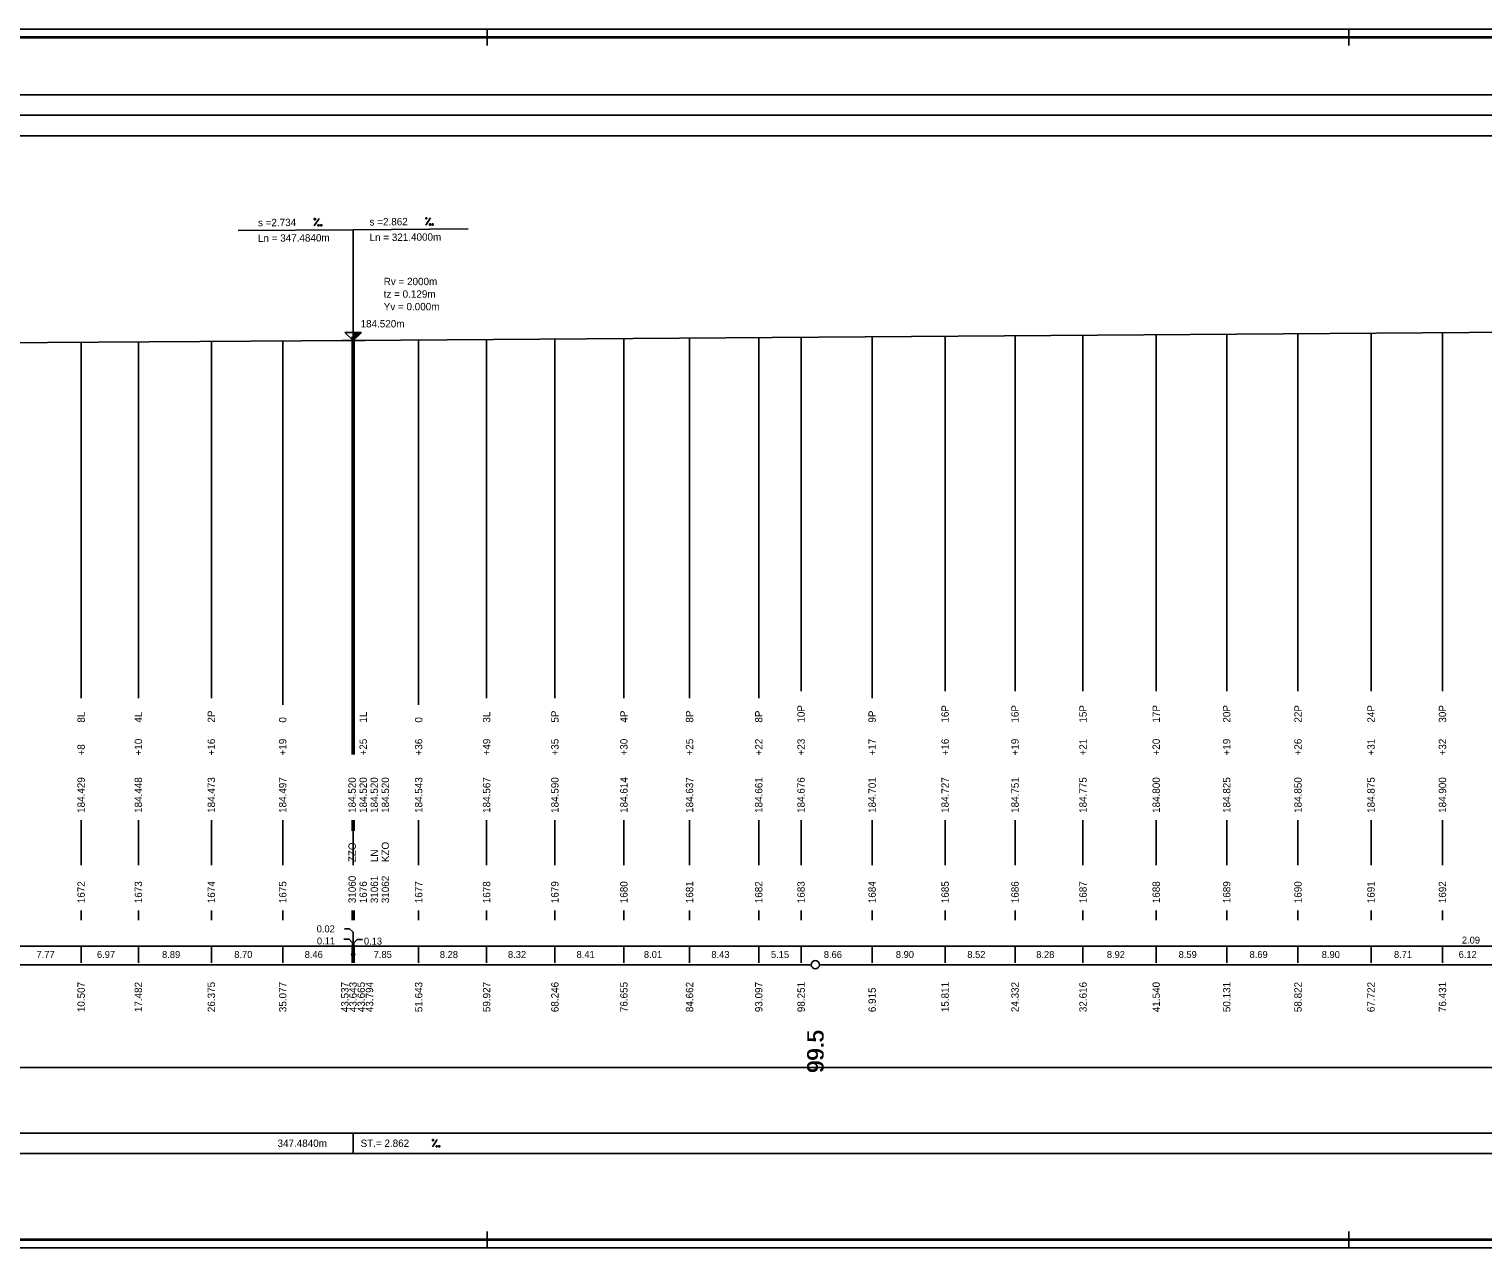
# Model space of a CAD drawing. Extents: x 0 to 10087, y -805 to 297.
# Drawn here: x 6188.3 to 6542.7, y 0 to 297 of the extents above; entities that cross this region are included whole.
import ezdxf

# ---------------------------------------------------------------- set-up
doc = ezdxf.new("R2010")
doc.units = 0
for name, color, linetype in [('CARKY_HODNOT', 7, 'Continuous'), ('KRIV1_CARA', 7, 'Continuous'), ('NIVELETA_CARA', 7, 'Continuous'), ('NIVELETA_TEXT', 7, 'Continuous'), ('RAM', 7, 'Continuous'), ('REZERVA', 7, 'Continuous'), ('STAN_CARA', 7, 'Continuous'), ('STAN_PAS', 7, 'Continuous'), ('STAN_TEXT', 7, 'Continuous'), ('TEXT', 7, 'Continuous'), ('TXT_C_BODU', 7, 'Continuous')]:
    doc.layers.add(name, color=color, linetype=linetype)

msp = doc.modelspace()

# ---------------------------------------------------------------- linework, layer by layer
at = {"layer": 'CARKY_HODNOT'}
for p, q in [((6201.01, 138.35), (6201.01, 220.65)), ((6214.96, 138.35), (6214.96, 220.74)), ((6232.75, 138.35), (6232.75, 220.86)), ((6250.15, 138.35), (6250.15, 220.98)), ((6267.07, 138.35), (6267.07, 221.1)), ((6267.29, 138.35), (6267.29, 221.1)), ((6267.33, 138.35), (6267.33, 221.1)), ((6267.59, 138.35), (6267.59, 221.1)), ((6283.29, 138.35), (6283.29, 221.21)), ((6299.85, 138.35), (6299.85, 221.33)), ((6316.49, 138.35), (6316.49, 221.45)), ((6333.31, 138.35), (6333.31, 221.57)), ((6349.32, 138.35), (6349.32, 221.69)), ((6366.19, 138.35), (6366.19, 221.81)), ((6376.5, 138.35), (6376.5, 221.88)), ((6393.83, 138.35), (6393.83, 222.01)), ((6411.62, 138.35), (6411.62, 222.13)), ((6428.66, 138.35), (6428.66, 222.25)), ((6445.23, 138.35), (6445.23, 222.37)), ((6463.08, 138.35), (6463.08, 222.5)), ((6480.26, 138.35), (6480.26, 222.62)), ((6497.64, 138.35), (6497.64, 222.75)), ((6515.44, 138.35), (6515.44, 222.88)), ((6532.86, 138.35), (6532.86, 223)), ((6201.01, 134), (6201.01, 138.35)), ((6214.96, 134), (6214.96, 138.35)), ((6232.75, 134), (6232.75, 138.35)), ((6250.15, 132.35), (6250.15, 138.35)), ((6267.07, 126.2), (6267.07, 138.35)), ((6267.29, 134), (6267.29, 138.35)), ((6267.33, 126.2), (6267.33, 138.35)), ((6267.59, 126.2), (6267.59, 138.35)), ((6283.29, 132.35), (6283.29, 138.35)), ((6299.85, 134), (6299.85, 138.35)), ((6316.49, 134), (6316.49, 138.35)), ((6333.31, 134), (6333.31, 138.35)), ((6349.32, 134), (6349.32, 138.35)), ((6366.19, 134), (6366.19, 138.35)), ((6376.5, 135.65), (6376.5, 138.35)), ((6393.83, 134), (6393.83, 138.35)), ((6411.62, 135.65), (6411.62, 138.35)), ((6428.66, 135.65), (6428.66, 138.35)), ((6445.23, 135.65), (6445.23, 138.35)), ((6463.08, 135.65), (6463.08, 138.35)), ((6480.26, 135.65), (6480.26, 138.35)), ((6497.64, 135.65), (6497.64, 138.35)), ((6515.44, 135.65), (6515.44, 138.35)), ((6532.86, 135.65), (6532.86, 138.35)), ((6267.07, 120.25), (6267.07, 126.2)), ((6267.33, 120.25), (6267.33, 126.2)), ((6267.59, 120.25), (6267.59, 126.2)), ((6201.01, 93.3), (6201.01, 104.2)), ((6214.96, 93.3), (6214.96, 104.2)), ((6232.75, 93.3), (6232.75, 104.2)), ((6250.15, 93.3), (6250.15, 104.2)), ((6267.07, 101.65), (6267.07, 104.2)), ((6267.29, 93.3), (6267.29, 104.2)), ((6267.33, 100), (6267.33, 104.2)), ((6267.59, 101.65), (6267.59, 104.2)), ((6283.29, 93.3), (6283.29, 104.2)), ((6299.85, 93.3), (6299.85, 104.2)), ((6316.49, 93.3), (6316.49, 104.2)), ((6333.31, 93.3), (6333.31, 104.2)), ((6349.32, 93.3), (6349.32, 104.2)), ((6366.19, 93.3), (6366.19, 104.2)), ((6376.5, 93.3), (6376.5, 104.2)), ((6393.83, 93.3), (6393.83, 104.2)), ((6411.62, 93.3), (6411.62, 104.2)), ((6428.66, 93.3), (6428.66, 104.2)), ((6445.23, 93.3), (6445.23, 104.2)), ((6463.08, 93.3), (6463.08, 104.2)), ((6480.26, 93.3), (6480.26, 104.2)), ((6497.64, 93.3), (6497.64, 104.2)), ((6515.44, 93.3), (6515.44, 104.2)), ((6532.86, 93.3), (6532.86, 104.2)), ((6201.01, 79.9), (6201.01, 82.2)), ((6214.96, 79.9), (6214.96, 82.2)), ((6232.75, 79.9), (6232.75, 82.2)), ((6250.15, 79.9), (6250.15, 82.2)), ((6267.07, 79.9), (6267.07, 82.2)), ((6267.29, 79.9), (6267.29, 82.2)), ((6267.33, 79.9), (6267.33, 82.2)), ((6267.59, 79.9), (6267.59, 82.2)), ((6283.29, 79.9), (6283.29, 82.2)), ((6299.85, 79.9), (6299.85, 82.2)), ((6316.49, 79.9), (6316.49, 82.2)), ((6333.31, 79.9), (6333.31, 82.2)), ((6349.32, 79.9), (6349.32, 82.2)), ((6366.19, 79.9), (6366.19, 82.2)), ((6376.5, 79.9), (6376.5, 82.2)), ((6393.83, 79.9), (6393.83, 82.2)), ((6411.62, 79.9), (6411.62, 82.2)), ((6428.66, 79.9), (6428.66, 82.2)), ((6445.23, 79.9), (6445.23, 82.2)), ((6463.08, 79.9), (6463.08, 82.2)), ((6480.26, 79.9), (6480.26, 82.2)), ((6497.64, 79.9), (6497.64, 82.2)), ((6515.44, 79.9), (6515.44, 82.2)), ((6532.86, 79.9), (6532.86, 82.2))]:
    msp.add_line(p, q, dxfattribs=at)
at = {"layer": 'KRIV1_CARA'}
msp.add_line((5093.47, 44), (6545.11, 44), dxfattribs=at)
at = {"layer": 'NIVELETA_CARA'}
for p, q in [((300, 281), (8321.33, 281)), ((300, 276), (8321.33, 276)), ((300, 271), (8321.33, 271)), ((6267.33, 248.1), (6239.33, 247.91)), ((6267.33, 248.1), (6295.33, 248.3)), ((6267.33, 221.1), (6267.33, 248.1)), ((6267.59, 221.1), (6909.24, 225.69)), ((5576.72, 216.38), (6267.07, 221.1)), ((6267.07, 221.1), (6264.53, 221.08)), ((6267.33, 221.1), (6265.33, 223.1)), ((6265.33, 223.1), (6269.33, 223.1)), ((6267.07, 221.1), (6267.07, 222.1)), ((6267.07, 221.1), (6267.33, 221.1)), ((6267.33, 221.1), (6267.33, 223.1)), ((6269.33, 223.1), (6267.33, 221.1)), ((6267.33, 221.1), (6267.59, 221.1)), ((6267.4, 221.17), (6267.4, 223.1)), ((6267.46, 221.23), (6267.46, 223.1)), ((6267.53, 221.3), (6267.53, 223.1)), ((6267.59, 221.1), (6267.59, 222.1)), ((6270.13, 221.12), (6267.59, 221.1)), ((6267.6, 221.37), (6267.6, 223.1)), ((6267.66, 221.43), (6267.66, 223.1)), ((6267.73, 221.5), (6267.73, 223.1)), ((6267.8, 221.57), (6267.8, 223.1)), ((6267.86, 221.63), (6267.86, 223.1)), ((6267.93, 221.7), (6267.93, 223.1)), ((6268, 221.77), (6268, 223.1)), ((6268.06, 221.83), (6268.06, 223.1)), ((6268.13, 221.9), (6268.13, 223.1)), ((6268.2, 221.97), (6268.2, 223.1)), ((6268.26, 222.03), (6268.26, 223.1)), ((6268.33, 222.1), (6268.33, 223.1)), ((6268.4, 222.17), (6268.4, 223.1)), ((6268.46, 222.23), (6268.46, 223.1)), ((6268.53, 222.3), (6268.53, 223.1)), ((6268.6, 222.37), (6268.6, 223.1)), ((6268.66, 222.43), (6268.66, 223.1)), ((6268.73, 222.5), (6268.73, 223.1)), ((6268.8, 222.57), (6268.8, 223.1)), ((6268.86, 222.63), (6268.86, 223.1)), ((6268.93, 222.7), (6268.93, 223.1)), ((6269, 222.77), (6269, 223.1)), ((6269.06, 222.83), (6269.06, 223.1)), ((6269.13, 222.9), (6269.13, 223.1)), ((6269.2, 222.97), (6269.2, 223.1)), ((6269.26, 223.03), (6269.26, 223.1)), ((500, 28), (8321.33, 28)), ((6267.33, 23), (6267.33, 28)), ((500, 23), (8321.33, 23))]:
    msp.add_line(p, q, dxfattribs=at)
at = {"layer": 'NIVELETA_TEXT'}
for p, q in [((6257.82, 250.83), (6257.82, 250.53)), ((6257.83, 250.83), (6257.82, 250.83)), ((6257.82, 250.53), (6258.12, 250.54)), ((6257.83, 249.04), (6259.01, 250.84)), ((6258.12, 250.83), (6257.83, 250.83)), ((6258.12, 250.54), (6258.12, 250.83)), ((6258.74, 249.34), (6258.74, 249.04)), ((6259.04, 249.34), (6258.74, 249.34)), ((6258.74, 249.34), (6258.74, 249.34)), ((6258.74, 249.04), (6259.04, 249.05)), ((6259.04, 249.05), (6259.04, 249.34)), ((6259.36, 249.34), (6259.35, 249.34)), ((6259.35, 249.34), (6259.35, 249.05)), ((6259.35, 249.05), (6259.65, 249.05)), ((6259.65, 249.35), (6259.36, 249.34)), ((6259.65, 249.05), (6259.65, 249.35)), ((6285.02, 251.02), (6285.02, 250.73)), ((6285.03, 251.02), (6285.02, 251.02)), ((6285.02, 250.73), (6285.32, 250.73)), ((6285.03, 249.23), (6286.21, 251.03)), ((6285.32, 251.03), (6285.03, 251.02)), ((6285.32, 250.73), (6285.32, 251.03)), ((6285.94, 249.53), (6285.94, 249.24)), ((6286.24, 249.53), (6285.94, 249.53)), ((6285.94, 249.53), (6285.94, 249.53)), ((6285.94, 249.24), (6286.24, 249.24)), ((6286.24, 249.24), (6286.24, 249.53)), ((6286.55, 249.54), (6286.55, 249.24)), ((6286.56, 249.54), (6286.55, 249.53)), ((6286.55, 249.24), (6286.85, 249.24)), ((6286.85, 249.54), (6286.56, 249.54)), ((6286.85, 249.24), (6286.85, 249.54)), ((6286.63, 24.6), (6287.82, 26.4)), ((6286.63, 26.4), (6286.63, 26.1)), ((6286.64, 26.4), (6286.63, 26.39)), ((6286.63, 26.1), (6286.93, 26.1)), ((6286.93, 26.4), (6286.64, 26.4)), ((6286.93, 26.1), (6286.93, 26.4)), ((6287.54, 24.9), (6287.54, 24.6)), ((6287.55, 24.9), (6287.54, 24.89)), ((6287.84, 24.9), (6287.55, 24.9)), ((6287.84, 24.6), (6287.84, 24.9)), ((6288.15, 24.9), (6288.15, 24.6)), ((6288.16, 24.9), (6288.15, 24.89)), ((6288.45, 24.9), (6288.16, 24.9)), ((6288.45, 24.6), (6288.45, 24.9)), ((6287.54, 24.6), (6287.84, 24.6)), ((6288.15, 24.6), (6288.45, 24.6))]:
    msp.add_line(p, q, dxfattribs=at)
at = {"layer": 'RAM'}
for p, q in [((8636.33, 297), (0, 297)), ((8634.33, 295.1), (2, 295.1)), ((8634.33, 295), (2, 295)), ((8634.33, 294.9), (2, 294.9)), ((6300, 293), (6300, 297)), ((6510, 293), (6510, 297)), ((6300, 0), (6300, 4)), ((6510, 0), (6510, 4)), ((0, 0), (8636.33, 0)), ((2, 2.1), (8634.33, 2.1)), ((2, 2), (8634.33, 2)), ((2, 1.9), (8634.33, 1.9))]:
    msp.add_line(p, q, dxfattribs=at)
at = {"layer": 'REZERVA'}
msp.add_circle((6380, 69), 1, dxfattribs=at)
at = {"layer": 'STAN_CARA'}
for p, q in [((6181, 69), (6379, 69)), ((6381, 69), (6579, 69))]:
    msp.add_line(p, q, dxfattribs=at)
at = {"layer": 'STAN_PAS'}
for p, q in [((6266.33, 75.2), (6265.05, 75.2)), ((6266.46, 77.75), (6265.18, 77.75)), ((6267.18, 74.35), (6266.33, 75.2)), ((6267.31, 76.9), (6266.46, 77.75)), ((6267.31, 71.75), (6267.31, 76.9)), ((6267.46, 74.33), (6268.31, 75.17)), ((6268.31, 75.17), (6269.58, 75.17)), ((300, 73.5), (8321.33, 73.5)), ((6201.01, 69.5), (6201.01, 73.5)), ((6214.96, 69.5), (6214.96, 73.5)), ((6232.75, 69.5), (6232.75, 73.5)), ((6250.15, 69.5), (6250.15, 73.5)), ((6267.07, 69.5), (6267.07, 73.5)), ((6267.18, 71.75), (6267.18, 74.35)), ((6267.29, 69.5), (6267.29, 73.5)), ((6267.33, 69.5), (6267.33, 73.5)), ((6267.46, 71.75), (6267.46, 74.33)), ((6267.59, 69.5), (6267.59, 73.5)), ((6283.29, 69.5), (6283.29, 73.5)), ((6299.85, 69.5), (6299.85, 73.5)), ((6316.49, 69.5), (6316.49, 73.5)), ((6333.31, 69.5), (6333.31, 73.5)), ((6349.32, 69.5), (6349.32, 73.5)), ((6366.19, 69.5), (6366.19, 73.5)), ((6376.5, 69.5), (6376.5, 73.5)), ((6393.83, 69.5), (6393.83, 73.5)), ((6411.62, 69.5), (6411.62, 73.5)), ((6428.66, 69.5), (6428.66, 73.5)), ((6445.23, 69.5), (6445.23, 73.5)), ((6463.08, 69.5), (6463.08, 73.5)), ((6480.26, 69.5), (6480.26, 73.5)), ((6497.64, 69.5), (6497.64, 73.5)), ((6515.44, 69.5), (6515.44, 73.5)), ((6532.86, 69.5), (6532.86, 73.5))]:
    msp.add_line(p, q, dxfattribs=at)
for centre in [(6267.18, 71.5), (6267.31, 71.5), (6267.46, 71.5)]:
    msp.add_circle(centre, 0.25, dxfattribs=at)

# ---------------------------------------------------------------- texts
at = {"layer": 'NIVELETA_TEXT'}
for s, rotation, p in [('s =2.734', 0.3916, (6244.13, 248.94)), ('s =2.862', 0.41, (6271.33, 249.13)), ('Ln = 347.4840m', 0.3916, (6244.13, 245.14)), ('Ln = 321.4000m', 0.41, (6271.33, 245.33))]:
    msp.add_text(s, height=1.8, rotation=rotation, dxfattribs=at).set_placement(p)
for s, p in [('Rv = 2000m', (6274.77, 234.6)), ('tz = 0.129m', (6274.77, 231.54)), ('Yv = 0.000m', (6274.77, 228.48)), ('184.520m', (6269.13, 224.3)), ('347.4840m', (6248.88, 24.6)), ('ST.= 2.862', (6269.13, 24.6))]:
    msp.add_text(s, height=1.8, dxfattribs=at).set_placement(p)
at = {"layer": 'STAN_TEXT'}
for s, p in [('0.02', (6258.43, 76.9)), ('0.11', (6258.49, 73.95)), ('0.13', (6269.95, 73.91)), ('2.09', (6537.59, 74.16)), ('7.77', (6190.13, 70.65)), ('6.97', (6204.87, 70.65)), ('8.89', (6220.74, 70.65)), ('8.70', (6238.34, 70.65)), ('8.46', (6255.5, 70.65)), ('7.85', (6272.32, 70.65)), ('8.28', (6288.45, 70.65)), ('8.32', (6305.06, 70.65)), ('8.41', (6321.78, 70.65)), ('8.01', (6338.2, 70.65)), ('8.43', (6354.64, 70.65)), ('5.15', (6369.17, 70.64)), ('8.66', (6382.05, 70.65)), ('8.90', (6399.61, 70.65)), ('8.52', (6417.03, 70.65)), ('8.28', (6433.83, 70.65)), ('8.92', (6451.04, 70.65)), ('8.59', (6468.55, 70.65)), ('8.69', (6485.84, 70.65)), ('8.90', (6503.43, 70.65)), ('8.71', (6521.04, 70.65)), ('6.12', (6536.8, 70.66))]:
    msp.add_text(s, height=1.7, dxfattribs=at).set_placement(p)
for s, height, p in [('10.507', 1.8, (6201.91, 57.45)), ('17.482', 1.8, (6215.86, 57.45)), ('26.375', 1.8, (6233.65, 57.45)), ('35.077', 1.8, (6251.05, 57.45)), ('43.537', 1.8, (6266.19, 57.45)), ('43.643', 1.8, (6268.18, 57.45)), ('43.665', 1.8, (6270.18, 57.45)), ('43.794', 1.8, (6272.2, 57.45)), ('51.643', 1.8, (6284.19, 57.45)), ('59.927', 1.8, (6300.75, 57.45)), ('68.246', 1.8, (6317.39, 57.45)), ('76.655', 1.8, (6334.21, 57.45)), ('84.662', 1.8, (6350.22, 57.45)), ('93.097', 1.8, (6367.09, 57.45)), ('98.251', 1.8, (6377.42, 57.45)), ('15.811', 1.8, (6412.52, 57.45)), ('24.332', 1.8, (6429.56, 57.45)), ('32.616', 1.8, (6446.13, 57.45)), ('41.540', 1.8, (6463.98, 57.45)), ('50.131', 1.8, (6481.16, 57.45)), ('58.822', 1.8, (6498.54, 57.45)), ('67.722', 1.8, (6516.34, 57.45)), ('76.431', 1.8, (6533.76, 57.45)), ('6.915', 1.8, (6394.73, 57.45)), ('    99.5', 4, (6382, 36.84)), ('    99.5', 4, (6382, 36.74)), ('    99.5', 4, (6382, 36.64))]:
    msp.add_text(s, height=height, rotation=90, dxfattribs=at).set_placement(p)
at = {"layer": 'TEXT'}
for s, p in [('10P', (6377.4, 128)), ('16P', (6412.52, 128)), ('16P', (6429.56, 128)), ('15P', (6446.13, 128)), ('17P', (6463.98, 128)), ('20P', (6481.16, 128)), ('22P', (6498.54, 128)), ('24P', (6516.34, 128)), ('30P', (6533.76, 128)), ('8L', (6201.91, 128)), ('4L', (6215.86, 128)), ('2P', (6233.65, 128)), ('0', (6251.05, 128)), ('1L', (6270.67, 128)), ('0', (6284.19, 128)), ('3L', (6300.75, 128)), ('5P', (6317.39, 128)), ('4P', (6334.21, 128)), ('8P', (6350.22, 128)), ('8P', (6367.09, 128)), ('9P', (6394.73, 128)), ('+8', (6201.91, 120)), ('+10', (6215.86, 120)), ('+16', (6233.65, 120)), ('+19', (6251.05, 120)), ('+25', (6270.67, 120)), ('+36', (6284.19, 120)), ('+49', (6300.75, 120)), ('+35', (6317.39, 120)), ('+30', (6334.21, 120)), ('+25', (6350.22, 120)), ('+22', (6367.09, 120)), ('+23', (6377.4, 120)), ('+17', (6394.73, 120)), ('+16', (6412.52, 120)), ('+19', (6429.56, 120)), ('+21', (6446.13, 120)), ('+20', (6463.98, 120)), ('+19', (6481.16, 120)), ('+26', (6498.54, 120)), ('+31', (6516.34, 120)), ('+32', (6533.76, 120)), ('184.429', (6201.91, 106)), ('184.448', (6215.86, 106)), ('184.473', (6233.65, 106)), ('184.497', (6251.05, 106)), ('184.520', (6267.97, 106)), ('184.520', (6270.67, 106)), ('184.520', (6273.37, 106)), ('184.520', (6276.07, 106)), ('184.543', (6284.19, 106)), ('184.567', (6300.75, 106)), ('184.590', (6317.39, 106)), ('184.614', (6334.21, 106)), ('184.637', (6350.22, 106)), ('184.661', (6367.09, 106)), ('184.676', (6377.4, 106)), ('184.701', (6394.73, 106)), ('184.727', (6412.52, 106)), ('184.751', (6429.56, 106)), ('184.775', (6446.13, 106)), ('184.800', (6463.98, 106)), ('184.825', (6481.16, 106)), ('184.850', (6498.54, 106)), ('184.875', (6516.34, 106)), ('184.900', (6533.76, 106)), ('ZZO', (6267.97, 94)), ('LN', (6273.37, 94)), ('KZO', (6276.07, 94))]:
    msp.add_text(s, height=1.8, rotation=90, dxfattribs=at).set_placement(p)
at = {"layer": 'TXT_C_BODU'}
for s, p in [('1672', (6201.91, 84)), ('1673', (6215.86, 84)), ('1674', (6233.65, 84)), ('1675', (6251.05, 84)), ('31060', (6267.97, 84)), ('1676', (6270.67, 84)), ('31061', (6273.37, 84)), ('31062', (6276.07, 84)), ('1677', (6284.19, 84)), ('1678', (6300.75, 84)), ('1679', (6317.39, 84)), ('1680', (6334.21, 84)), ('1681', (6350.22, 84)), ('1682', (6367.09, 84)), ('1683', (6377.4, 84)), ('1684', (6394.73, 84)), ('1685', (6412.52, 84)), ('1686', (6429.56, 84)), ('1687', (6446.13, 84)), ('1688', (6463.98, 84)), ('1689', (6481.16, 84)), ('1690', (6498.54, 84)), ('1691', (6516.34, 84)), ('1692', (6533.76, 84))]:
    msp.add_text(s, height=1.8, rotation=90, dxfattribs=at).set_placement(p)

doc.saveas('drawing.dxf')
